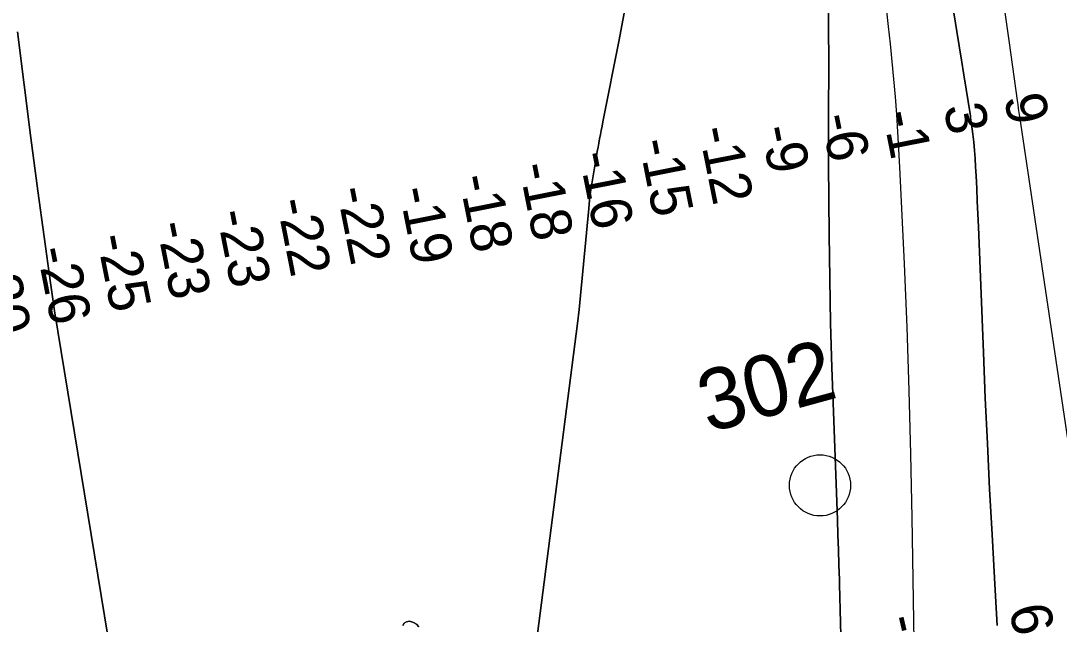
# Model space of a CAD drawing. Extents: x 3161665 to 3199565, y 885729 to 911164.
# Drawn here: x 3176516 to 3178214, y 895980 to 896967 of the extents above; entities that cross this region are included whole.
import ezdxf

# ---------------------------------------------------------------- set-up
doc = ezdxf.new("R2010")
doc.units = 0
for name, color, linetype in [('V-RIVR-IDEN', 7, 'Continuous'), ('V-RIVR-MILE', 7, 'Continuous'), ('V-RIVR-RANG', 7, 'Continuous'), ('V-TOPO-DPTH', 7, 'Continuous'), ('V-TOPO-MINR', 7, 'Continuous')]:
    doc.layers.add(name, color=color, linetype=linetype)

msp = doc.modelspace()

# ---------------------------------------------------------------- linework, layer by layer
at = {"layer": 'V-RIVR-MILE'}
msp.add_circle((3177822.699, 896206.927), 50.0000000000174, dxfattribs=at)
at = {"layer": 'V-TOPO-DPTH'}
for points in [[(3178112.6411395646, 895977.8544873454), (3178110.842154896, 896006.7218272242), (3178109.1476796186, 896035.5959649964), (3178104.0557494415, 896126.5879572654), (3178100.0762901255, 896200.9719103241), (3178096.3402754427, 896275.3674899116), (3178092.969427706, 896349.7805092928), (3178089.8420246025, 896424.2051552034), (3178081.7070609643, 896629.8254979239), (3178080.8463813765, 896650.6439178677), (3178079.9364055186, 896671.4600950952), (3178078.952485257, 896692.272908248), (3178077.9192687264, 896713.0834786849), (3178077.1557506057, 896727.9294089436), (3178076.320336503, 896741.3023554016), (3178075.289164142, 896754.658018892), (3178073.9643543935, 896767.9877579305), (3178072.4437863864, 896781.3002140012), (3178069.952714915, 896801.1676401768), (3178069.5142207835, 896804.5310659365), (3178069.0537602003, 896807.8913717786), (3178068.5603499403, 896811.2469977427), (3178068.044973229, 896814.599503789), (3178061.6467572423, 896854.9019811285), (3178057.9099990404, 896878.4024605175), (3178054.165514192, 896901.9017067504), (3178050.409439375, 896925.3991032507), (3178046.6456379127, 896948.8952665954), (3177941.9240149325, 897601.6069131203)], [(3177941.9240149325, 897601.6069131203), (3178046.6456379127, 896948.8952665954), (3178050.409439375, 896925.3991032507), (3178054.165514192, 896901.9017067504), (3178057.9099990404, 896878.4024605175), (3178061.6467572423, 896854.9019811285), (3178068.044973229, 896814.599503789), (3178068.5603499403, 896811.2469977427), (3178069.0537602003, 896807.8913717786), (3178069.5142207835, 896804.5310659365), (3178069.952714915, 896801.1676401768), (3178072.4437863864, 896781.3002140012), (3178073.9643543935, 896767.9877579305), (3178075.289164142, 896754.658018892), (3178076.320336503, 896741.3023554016), (3178077.1557506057, 896727.9294089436), (3178077.9192687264, 896713.0834786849), (3178078.952485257, 896692.272908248), (3178079.9364055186, 896671.4600950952), (3178080.8463813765, 896650.6439178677), (3178081.7070609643, 896629.8254979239), (3178089.8420246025, 896424.2051552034), (3178092.969427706, 896349.7805092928), (3178096.3402754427, 896275.3674899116), (3178100.0762901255, 896200.9719103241), (3178104.0557494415, 896126.5879572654), (3178109.1476796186, 896035.5959649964), (3178110.842154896, 896006.7218272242), (3178112.6411395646, 895977.8544873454)], [(3177335.7136092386, 895769.4156468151), (3177426.2768039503, 896471.6272608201), (3177428.79345984, 896494.5529022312), (3177431.113989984, 896517.5013486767), (3177444.5724070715, 896659.7130591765), (3177445.992150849, 896673.1022104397), (3177447.6126548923, 896686.4647129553), (3177449.5342993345, 896699.7872423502), (3177451.6567040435, 896713.0831229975), (3177457.25196766, 896745.7610865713), (3177458.467747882, 896752.704671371), (3177459.7182542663, 896759.6418615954), (3177461.0208498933, 896766.5694599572), (3177462.35817168, 896773.490663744), (3177463.7211921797, 896780.4071397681), (3177465.0837469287, 896787.32370752), (3177466.4456030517, 896794.2404128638), (3177467.806993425, 896801.1572099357), (3177494.1782761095, 896935.1771381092), (3177600.946914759, 897508.1896997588)], [(3177600.946914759, 897508.1896997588), (3177494.1782761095, 896935.1771381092), (3177467.806993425, 896801.1572099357), (3177466.4456030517, 896794.2404128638), (3177465.0837469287, 896787.32370752), (3177463.7211921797, 896780.4071397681), (3177462.35817168, 896773.490663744), (3177461.0208498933, 896766.5694599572), (3177459.7182542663, 896759.6418615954), (3177458.467747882, 896752.704671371), (3177457.25196766, 896745.7610865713), (3177451.6567040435, 896713.0831229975), (3177449.5342993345, 896699.7872423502), (3177447.6126548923, 896686.4647129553), (3177445.992150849, 896673.1022104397), (3177444.5724070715, 896659.7130591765), (3177431.113989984, 896517.5013486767), (3177428.79345984, 896494.5529022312), (3177426.2768039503, 896471.6272608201), (3177335.7136092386, 895769.4156468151)], [(3177836.3474722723, 896982.241415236), (3177836.7100848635, 896945.6175398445), (3177836.934272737, 896908.9932095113), (3177836.950823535, 896872.3681967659), (3177836.8289496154, 896835.7427290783), (3177836.5644727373, 896792.8243779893), (3177836.5056879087, 896777.6577951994), (3177836.493136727, 896762.4912798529), (3177836.5499360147, 896747.3248656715), (3177836.6529689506, 896732.1585189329), (3177837.6960712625, 896617.279308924), (3177838.668124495, 896544.6807416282), (3177840.0571623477, 896472.0919511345), (3177842.071677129, 896399.5178258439), (3177844.5031765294, 896326.9534773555), (3177851.1741731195, 896150.577325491), (3177852.074804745, 896126.0192907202), (3177852.937863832, 896101.4599787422), (3177853.7445641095, 896076.898750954), (3177854.5136918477, 896052.3362459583), (3177854.730345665, 896045.1538686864), (3177855.326785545, 896024.1807112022), (3177855.8749851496, 896003.2063761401), (3177856.350824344, 895982.2302747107), (3177856.7784232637, 895961.2529957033)], [(3177836.3474722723, 896982.241415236), (3177836.7100848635, 896945.6175398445), (3177836.934272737, 896908.9932095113), (3177836.950823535, 896872.3681967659), (3177836.8289496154, 896835.7427290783), (3177836.5644727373, 896792.8243779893), (3177836.5056879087, 896777.6577951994), (3177836.493136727, 896762.4912798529), (3177836.5499360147, 896747.3248656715), (3177836.6529689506, 896732.1585189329), (3177837.6960712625, 896617.279308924), (3177838.668124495, 896544.6807416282), (3177840.0571623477, 896472.0919511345), (3177842.071677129, 896399.5178258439), (3177844.5031765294, 896326.9534773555), (3177851.1741731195, 896150.577325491), (3177852.074804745, 896126.0192907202), (3177852.937863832, 896101.4599787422), (3177853.7445641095, 896076.898750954), (3177854.5136918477, 896052.3362459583), (3177854.730345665, 896045.1538686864), (3177855.326785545, 896024.1807112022), (3177855.8749851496, 896003.2063761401), (3177856.350824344, 895982.2302747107), (3177856.7784232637, 895961.2529957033)], [(3176696.156886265, 895727.5087171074), (3176571.2286196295, 896492.0598042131), (3176569.4090173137, 896503.4860471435), (3176567.651169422, 896514.9215271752), (3176565.9859531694, 896526.3708628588), (3176564.3824913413, 896537.8294356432), (3176543.9489654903, 896688.2852570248), (3176532.4379955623, 896775.0116784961), (3176521.27757183, 896861.7821083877), (3176510.6429673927, 896948.61855091)], [(3176510.6429673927, 896948.61855091), (3176521.27757183, 896861.7821083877), (3176532.4379955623, 896775.0116784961), (3176543.9489654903, 896688.2852570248), (3176564.3824913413, 896537.8294356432), (3176565.9859531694, 896526.3708628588), (3176567.651169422, 896514.9215271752), (3176569.4090173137, 896503.4860471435), (3176571.2286196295, 896492.0598042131), (3176696.156886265, 895727.5087171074)], [(3177140.610587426, 895978.0027162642), (3177142.785259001, 895981.8389399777), (3177146.681989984, 895983.9032307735), (3177151.726760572, 895984.7862329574), (3177157.731458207, 895982.8878444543), (3177162.9136973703, 895979.9698598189), (3177166.862248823, 895975.5224809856)], [(3177166.862248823, 895975.5224809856), (3177162.9136973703, 895979.9698598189), (3177157.731458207, 895982.8878444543), (3177151.726760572, 895984.7862329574), (3177146.681989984, 895983.9032307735), (3177142.785259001, 895981.8389399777), (3177140.610587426, 895978.0027162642)]]:
    msp.add_lwpolyline(points, dxfattribs=at)
at = {"layer": 'V-TOPO-MINR'}
for points in [[(3177976.697404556, 895952.0490213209), (3177973.571543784, 896154.3247767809), (3177971.4807912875, 896258.129303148), (3177968.741664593, 896361.9136764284), (3177965.0299766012, 896465.667820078), (3177960.6699144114, 896569.4018106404), (3177953.302895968, 896727.0636358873), (3177951.8041204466, 896755.9112628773), (3177950.104902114, 896784.7460285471), (3177948.105019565, 896813.5615022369), (3177945.904694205, 896842.3641146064), (3177943.4350937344, 896871.1457194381), (3177940.806978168, 896899.9121811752), (3177937.941089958, 896928.6559282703), (3177934.9166866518, 896957.3845322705), (3177867.408542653, 897574.1384832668), (3177863.4913699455, 897608.8594609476), (3177859.420624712, 897643.5619067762), (3177855.119520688, 897678.2365548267), (3177850.664844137, 897712.8926710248), (3177768.305226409, 898337.2257683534)], [(3178248.9397078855, 896140.1080694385), (3178149.456821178, 896809.9864307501), (3178148.4826740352, 896816.5907544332), (3178147.51721106, 896823.1963386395), (3178146.5647743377, 896829.8038136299), (3178145.621021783, 896836.4125491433), (3178132.297540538, 896930.3735611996), (3178124.7462508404, 896983.9703663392), (3178117.2585477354, 897037.5759956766), (3178109.8662245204, 897091.194861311), (3178102.537487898, 897144.8225511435), (3178036.7172564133, 897629.6735479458), (3178033.628216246, 897651.1601703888), (3178030.3147190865, 897672.6103118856), (3178026.664536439, 897694.0057319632), (3178022.789896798, 897715.3646710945), (3178003.9703778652, 897814.6577553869)], [(3178112.6411395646, 895977.8544873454), (3178110.842154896, 896006.7218272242), (3178109.1476796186, 896035.5959649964), (3178104.0557494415, 896126.5879572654), (3178100.0762901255, 896200.9719103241), (3178096.3402754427, 896275.3674899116), (3178092.969427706, 896349.7805092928), (3178089.8420246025, 896424.2051552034), (3178081.7070609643, 896629.8254979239), (3178080.8463813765, 896650.6439178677), (3178079.9364055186, 896671.4600950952), (3178078.952485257, 896692.272908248), (3178077.9192687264, 896713.0834786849), (3178077.1557506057, 896727.9294089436), (3178076.320336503, 896741.3023554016), (3178075.289164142, 896754.658018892), (3178073.9643543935, 896767.9877579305), (3178072.4437863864, 896781.3002140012), (3178069.952714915, 896801.1676401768), (3178069.5142207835, 896804.5310659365), (3178069.0537602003, 896807.8913717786), (3178068.5603499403, 896811.2469977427), (3178068.044973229, 896814.599503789), (3178061.6467572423, 896854.9019811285), (3178057.9099990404, 896878.4024605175), (3178054.165514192, 896901.9017067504), (3178050.409439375, 896925.3991032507), (3178046.6456379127, 896948.8952665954), (3177941.9240149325, 897601.6069131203)], [(3177600.946914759, 897508.1896997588), (3177494.1782761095, 896935.1771381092), (3177467.806993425, 896801.1572099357), (3177466.4456030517, 896794.2404128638), (3177465.0837469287, 896787.32370752), (3177463.7211921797, 896780.4071397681), (3177462.35817168, 896773.490663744), (3177461.0208498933, 896766.5694599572), (3177459.7182542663, 896759.6418615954), (3177458.467747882, 896752.704671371), (3177457.25196766, 896745.7610865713), (3177451.6567040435, 896713.0831229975), (3177449.5342993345, 896699.7872423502), (3177447.6126548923, 896686.4647129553), (3177445.992150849, 896673.1022104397), (3177444.5724070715, 896659.7130591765), (3177431.113989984, 896517.5013486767), (3177428.79345984, 896494.5529022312), (3177426.2768039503, 896471.6272608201), (3177335.7136092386, 895769.4156468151)], [(3177856.7784232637, 895961.2529957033), (3177856.350824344, 895982.2302747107), (3177855.8749851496, 896003.2063761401), (3177855.326785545, 896024.1807112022), (3177854.730345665, 896045.1538686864), (3177854.5136918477, 896052.3362459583), (3177853.7445641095, 896076.898750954), (3177852.937863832, 896101.4599787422), (3177852.074804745, 896126.0192907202), (3177851.1741731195, 896150.577325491), (3177844.5031765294, 896326.9534773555), (3177842.071677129, 896399.5178258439), (3177840.0571623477, 896472.0919511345), (3177838.668124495, 896544.6807416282), (3177837.6960712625, 896617.279308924), (3177836.6529689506, 896732.1585189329), (3177836.5499360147, 896747.3248656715), (3177836.493136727, 896762.4912798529), (3177836.5056879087, 896777.6577951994), (3177836.5644727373, 896792.8243779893), (3177836.8289496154, 896835.7427290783), (3177836.950823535, 896872.3681967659), (3177836.934272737, 896908.9932095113), (3177836.7100848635, 896945.6175398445), (3177836.3474722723, 896982.241415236)], [(3176510.6429673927, 896948.61855091), (3176521.27757183, 896861.7821083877), (3176532.4379955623, 896775.0116784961), (3176543.9489654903, 896688.2852570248), (3176564.3824913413, 896537.8294356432), (3176565.9859531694, 896526.3708628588), (3176567.651169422, 896514.9215271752), (3176569.4090173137, 896503.4860471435), (3176571.2286196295, 896492.0598042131), (3176696.156886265, 895727.5087171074)], [(3177166.862248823, 895975.5224809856), (3177162.9136973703, 895979.9698598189), (3177157.731458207, 895982.8878444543), (3177151.726760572, 895984.7862329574), (3177146.681989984, 895983.9032307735), (3177142.785259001, 895981.8389399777), (3177140.610587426, 895978.0027162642)]]:
    msp.add_lwpolyline(points, dxfattribs=at)

# ---------------------------------------------------------------- texts
at = {"layer": 'V-RIVR-IDEN'}
msp.add_text('302', height=99.99980199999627, rotation=15.366149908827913, dxfattribs=at).set_placement((3177639.8892816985, 896292.3642022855))
at = {"layer": 'V-RIVR-RANG'}
for s, height, rotation, p in [('9', 67.00000000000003, 281.1827777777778, (3178123.3325231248, 896841.5083570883)), ('3', 67.00000000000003, 281.1827777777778, (3178024.517478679, 896825.7213836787)), ('-6', 67.00000000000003, 281.1827777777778, (3177823.7176393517, 896810.1902559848)), ('-1', 67.00000000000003, 281.1827777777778, (3177924.5779744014, 896815.6273783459)), ('-12', 67.00000000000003, 281.1827777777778, (3177623.940945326, 896789.4847027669)), ('-9', 67.00000000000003, 281.1827777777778, (3177725.6197966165, 896790.7804847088)), ('-15', 67.00000000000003, 281.1827777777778, (3177525.9965743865, 896769.2986176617)), ('-16', 67.00000000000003, 281.1827777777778, (3177428.154517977, 896748.5949900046)), ('-18', 67.00000000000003, 281.1827777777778, (3177329.9032034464, 896729.9615325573)), ('-18', 67.00000000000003, 281.1827777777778, (3177231.7542034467, 896710.8095325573)), ('-22', 67.00000000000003, 281.1827777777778, (3177031.7728803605, 896691.1390644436)), ('-19', 67.00000000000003, 281.1827777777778, (3177133.758675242, 896690.8822187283)), ('-22', 67.00000000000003, 281.1827777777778, (3176933.6238803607, 896671.9880644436)), ('-23', 67.00000000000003, 281.1827777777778, (3176835.37256583, 896653.3546069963)), ('-23', 67.00000000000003, 281.1827777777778, (3176737.2235658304, 896634.2026069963)), ('-25', 67.00000000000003, 281.1827777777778, (3176639.3815094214, 896613.4989793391)), ('-26', 67.00000000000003, 281.1827777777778, (3176541.5394530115, 896592.795351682)), ('-30', 67.00000000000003, 281.1827777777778, (3176443.134666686, 896574.9382080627)), ('6', 67, 283.07916666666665, (3178130.937794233, 896005.5635335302)), ('-2', 67, 283.07916666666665, (3177929.4486132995, 895989.0465641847))]:
    msp.add_text(s, height=height, rotation=rotation, dxfattribs=at).set_placement(p)

doc.saveas('drawing.dxf')
